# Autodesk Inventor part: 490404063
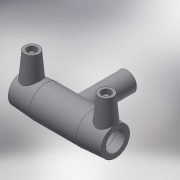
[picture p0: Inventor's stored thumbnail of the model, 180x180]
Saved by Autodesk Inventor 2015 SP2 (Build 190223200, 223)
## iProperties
Created: 2017-06
Part Number: 490404063
Material: Generic
Description: PLASSON TEE 63-63-63
Document SubType Name: Modeling
Designer: KIM
Mass: 57.3761 g
Surface Area: 241.06 cm^2
Volume: 57.3761 cm^3
Density: 1 g/cm^3
Appearance: Default
Author: KIM
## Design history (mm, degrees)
derived "490404.ipt"
feature "Solid1::490404.ipt"
tag "TaggingFeature1"
body "Solid1"
other parameters: "d0" = 167, "d1" = 63, "d2" = 82, "d3" = 58, "d4" = 41.75, "d5" = 73.8, "d6" = 59.85, "d7" = 63, "d8" = 168 deg, "d10" = 23.2, "d11" = 7.73333, "d13" = 167, "d14" = 17.6296, "d17" = 56.7, "d18" = 63, "d19" = 3.52592, "d20" = 168 deg, "d22" = 76.26, "d23" = 82, "d24" = 73.9722, "d25" = 135 deg, "d26" = 116.9, "d27" = 135 deg, "d29" = 58, "d30" = 15, "d31" = 66.8, "d34" = 5 deg, "d35" = 15, "d39" = 5 deg, "d40" = 9.6, "d41" = 4.8, "d42" = 6, "d43" = 0, "d45" = 4, "d46" = 14, "d47" = 0, "d48" = -119, "d49" = 63, "d51" = 0, "d52" = 50.4, "d54" = 0, "d55" = 73.8, "d56" = 82, "d57" = 58.45, "d58" = 135 deg, "d59" = 58, "d60" = 58, "d61" = 135 deg, "d62" = 119, "d72" = 75.985, "d73" = 37.9925, "d74" = -119, "d75" = 66.15, "d77" = 0, "d78" = 50.4, "d80" = 0, "d81" = 63, "d82" = 78, "d83" = 0, "d84" = 3, "d85" = 0, "d86" = 3, "d87" = 0, "d88" = 16.82, "d89" = 4.205, "d90" = 16.82, "d_" = 63, "L_" = 167, "L_1" = 58, "D_" = 82, "A_" = 58, "d_2" = 12, "H_" = 119
